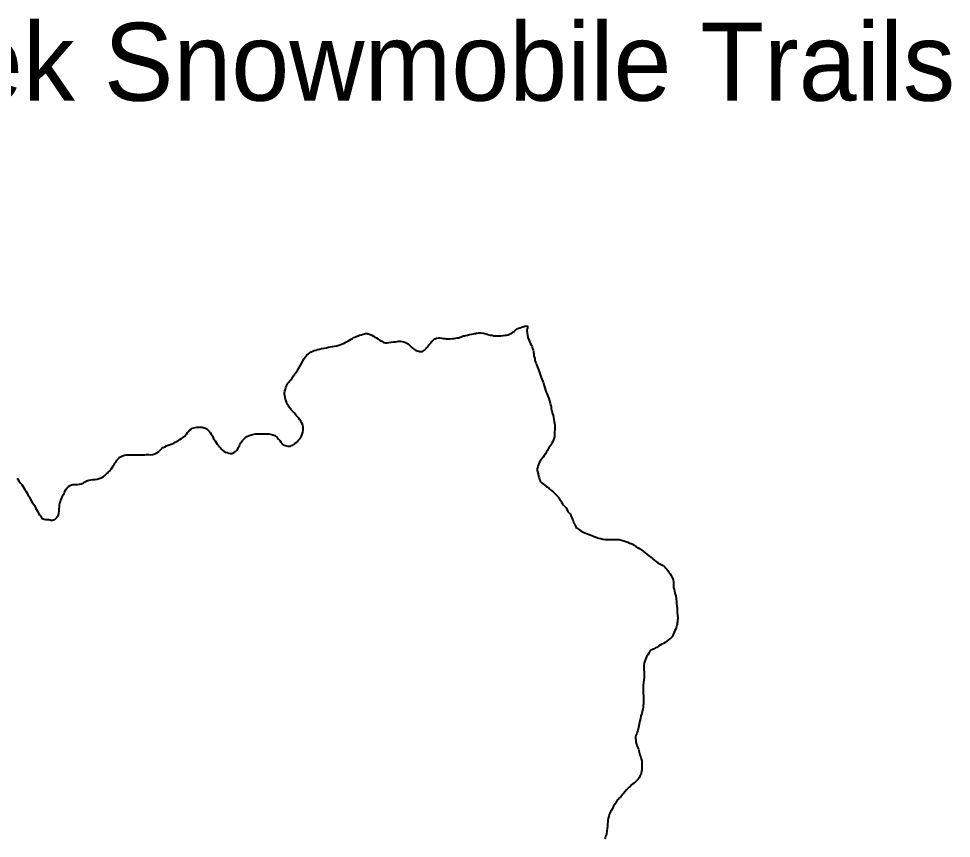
# Model space of a CAD drawing. Extents: x 322505 to 642419, y 5806860 to 5919753.
# Drawn here: x 555988 to 559579, y 5867430 to 5870588 of the extents above; entities that cross this region are included whole.
import ezdxf

# ---------------------------------------------------------------- set-up
doc = ezdxf.new("R2010")
doc.units = 0
doc.header["$LTSCALE"] = 140
doc.layers.add('5', color=7, linetype='Continuous', lineweight=40)

msp = doc.modelspace()

# ---------------------------------------------------------------- linework, layer by layer
at = {"layer": '5'}
for points in [[(557683, 5869358), (557697, 5869365), (557701, 5869366), (557705, 5869366), (557708, 5869367), (557716, 5869369), (557724, 5869371), (557732, 5869372), (557739, 5869374), (557744, 5869375), (557747, 5869375), (557750, 5869376), (557754, 5869376), (557758, 5869377), (557763, 5869377), (557769, 5869377), (557776, 5869376), (557782, 5869375), (557787, 5869374), (557792, 5869372), (557798, 5869370), (557804, 5869369), (557811, 5869368), (557818, 5869366), (557824, 5869366), (557831, 5869366), (557838, 5869366), (557845, 5869366), (557853, 5869367), (557861, 5869368), (557867, 5869369), (557873, 5869370), (557878, 5869372), (557883, 5869375), (557888, 5869378), (557892, 5869381), (557897, 5869384), (557901, 5869388), (557906, 5869391), (557909, 5869394), (557914, 5869396), (557921, 5869398), (557929, 5869401), (557937, 5869403), (557947, 5869405)], [(557947, 5869405), (557947, 5869403), (557947, 5869400), (557947, 5869397), (557946, 5869393), (557945, 5869386), (557946, 5869377), (557947, 5869368), (557949, 5869359), (557952, 5869351), (557955, 5869344), (557958, 5869338), (557962, 5869331), (557965, 5869323), (557967, 5869317), (557969, 5869311), (557970, 5869305), (557971, 5869300), (557972, 5869296), (557972, 5869291), (557973, 5869285), (557975, 5869278), (557976, 5869271), (557978, 5869265), (557980, 5869259), (557982, 5869254), (557984, 5869249), (557986, 5869245), (557988, 5869239), (557992, 5869228), (557996, 5869217), (558000, 5869206), (558004, 5869196), (558007, 5869188), (558009, 5869182), (558011, 5869174), (558014, 5869166), (558017, 5869157), (558019, 5869149), (558023, 5869141), (558026, 5869133), (558029, 5869125), (558032, 5869116), (558035, 5869107), (558036, 5869100), (558038, 5869093), (558039, 5869086), (558040, 5869081), (558041, 5869077), (558042, 5869072), (558044, 5869066), (558046, 5869059), (558048, 5869051), (558049, 5869044), (558050, 5869036), (558051, 5869029), (558052, 5869021), (558052, 5869013), (558052, 5869005), (558051, 5868998), (558051, 5868992), (558051, 5868987), (558051, 5868981), (558051, 5868977), (558050, 5868973), (558048, 5868966), (558045, 5868959), (558041, 5868952), (558037, 5868945), (558033, 5868940), (558030, 5868934), (558027, 5868930), (558024, 5868924), (558020, 5868919), (558016, 5868912), (558012, 5868905), (558007, 5868898), (558003, 5868892), (557999, 5868887), (557996, 5868883), (557994, 5868879), (557991, 5868873), (557988, 5868868), (557987, 5868862), (557986, 5868858), (557985, 5868855), (557985, 5868851), (557985, 5868847), (557986, 5868843), (557988, 5868834), (557990, 5868826), (557992, 5868819), (557994, 5868812), (557996, 5868807), (557999, 5868804), (558004, 5868799), (558009, 5868795), (558015, 5868790), (558021, 5868786), (558025, 5868783)], [(557255, 5869345), (557262, 5869349), (557268, 5869353), (557274, 5869356), (557278, 5869359), (557283, 5869361), (557288, 5869364), (557295, 5869366), (557301, 5869368), (557308, 5869370), (557314, 5869372), (557320, 5869374), (557323, 5869375), (557326, 5869375), (557330, 5869375), (557334, 5869374), (557339, 5869372), (557348, 5869369), (557355, 5869365), (557360, 5869361), (557366, 5869358), (557372, 5869354), (557376, 5869350), (557382, 5869347), (557387, 5869345), (557391, 5869342), (557395, 5869340), (557400, 5869339), (557407, 5869339), (557414, 5869340), (557422, 5869341), (557431, 5869343), (557439, 5869343), (557446, 5869344), (557452, 5869345), (557458, 5869345), (557465, 5869344), (557471, 5869343), (557477, 5869340), (557483, 5869338), (557488, 5869335), (557491, 5869332), (557496, 5869327), (557502, 5869321), (557508, 5869316), (557516, 5869311), (557524, 5869308), (557529, 5869307), (557532, 5869306), (557536, 5869305), (557540, 5869306), (557543, 5869306), (557547, 5869308), (557551, 5869311), (557554, 5869314), (557557, 5869317), (557559, 5869320), (557562, 5869323), (557565, 5869327), (557569, 5869332), (557572, 5869337), (557577, 5869341), (557581, 5869345), (557583, 5869348), (557586, 5869351), (557589, 5869354), (557592, 5869355), (557597, 5869357), (557604, 5869358), (557610, 5869358), (557617, 5869357), (557624, 5869356), (557629, 5869356), (557634, 5869355), (557638, 5869355), (557644, 5869355), (557650, 5869355), (557658, 5869356), (557665, 5869356), (557671, 5869357), (557677, 5869358), (557683, 5869358)], [(556931, 5868989), (556952, 5868988), (556963, 5868986), (556974, 5868982), (556984, 5868974), (556989, 5868968), (556994, 5868963), (556998, 5868957), (557001, 5868952), (557005, 5868948), (557009, 5868945), (557014, 5868943), (557019, 5868942), (557025, 5868941), (557030, 5868941), (557035, 5868941), (557039, 5868943), (557044, 5868945), (557048, 5868948), (557053, 5868952), (557059, 5868957), (557064, 5868963), (557069, 5868968), (557073, 5868972), (557076, 5868977), (557077, 5868980), (557079, 5868983), (557080, 5868987), (557081, 5868991), (557082, 5868995), (557083, 5869002), (557084, 5869009), (557084, 5869016), (557082, 5869023), (557079, 5869030), (557075, 5869037), (557071, 5869043), (557067, 5869049), (557062, 5869054), (557058, 5869058), (557054, 5869063), (557049, 5869069), (557044, 5869074), (557039, 5869080), (557034, 5869086), (557030, 5869091), (557027, 5869096), (557023, 5869101), (557021, 5869107), (557018, 5869115), (557016, 5869122), (557014, 5869129), (557013, 5869135), (557012, 5869141), (557012, 5869147), (557013, 5869153), (557015, 5869160), (557017, 5869167), (557019, 5869173), (557022, 5869179), (557025, 5869183), (557028, 5869188), (557032, 5869192), (557036, 5869197), (557041, 5869203), (557047, 5869212), (557052, 5869219), (557057, 5869226), (557062, 5869233), (557067, 5869241), (557072, 5869251), (557077, 5869260), (557082, 5869269), (557086, 5869277), (557092, 5869285), (557096, 5869289), (557099, 5869294), (557104, 5869297), (557109, 5869301), (557115, 5869304), (557121, 5869307), (557126, 5869310), (557132, 5869311), (557139, 5869313), (557146, 5869315), (557156, 5869317), (557165, 5869319), (557173, 5869320), (557180, 5869322), (557188, 5869323), (557196, 5869325), (557204, 5869326), (557213, 5869328), (557221, 5869330), (557229, 5869332), (557235, 5869335), (557241, 5869338), (557248, 5869341), (557255, 5869345)], [(556635, 5868987), (556638, 5868993), (556642, 5868997), (556646, 5869002), (556652, 5869006), (556658, 5869010), (556663, 5869012), (556668, 5869013), (556674, 5869014), (556681, 5869014), (556684, 5869014)], [(556684, 5869014), (556686, 5869014), (556690, 5869014), (556695, 5869014), (556699, 5869013), (556703, 5869012), (556708, 5869010), (556713, 5869008), (556717, 5869004), (556722, 5868999), (556726, 5868993), (556730, 5868987), (556734, 5868981), (556736, 5868977), (556738, 5868971), (556741, 5868967), (556745, 5868961), (556749, 5868955), (556753, 5868949), (556757, 5868944), (556762, 5868939), (556765, 5868934), (556769, 5868929), (556773, 5868925), (556779, 5868921), (556785, 5868918), (556791, 5868916), (556797, 5868914), (556802, 5868913), (556808, 5868913), (556809, 5868913)], [(556809, 5868913), (556813, 5868914), (556818, 5868916), (556823, 5868921), (556828, 5868926), (556832, 5868931), (556835, 5868937), (556838, 5868942), (556840, 5868948), (556842, 5868953), (556846, 5868958), (556850, 5868963), (556856, 5868969), (556861, 5868974), (556867, 5868978), (556873, 5868981), (556879, 5868983), (556889, 5868986), (556900, 5868988), (556910, 5868988), (556920, 5868989), (556931, 5868989)], [(556122, 5868657), (556127, 5868658), (556130, 5868661), (556133, 5868664), (556136, 5868668), (556138, 5868670), (556140, 5868673), (556142, 5868677), (556143, 5868683), (556144, 5868691), (556144, 5868699), (556145, 5868707), (556145, 5868714), (556147, 5868721), (556149, 5868727), (556151, 5868734), (556154, 5868741), (556157, 5868748), (556160, 5868754), (556163, 5868759), (556165, 5868764), (556167, 5868769), (556171, 5868775), (556175, 5868781), (556180, 5868786), (556186, 5868790), (556192, 5868792), (556197, 5868793), (556202, 5868793), (556208, 5868793), (556215, 5868793), (556222, 5868794), (556229, 5868796), (556236, 5868799), (556241, 5868802), (556246, 5868805), (556251, 5868807), (556258, 5868810), (556266, 5868811), (556274, 5868812), (556283, 5868812), (556291, 5868814), (556298, 5868816), (556306, 5868819), (556313, 5868823), (556320, 5868828), (556327, 5868834), (556331, 5868838), (556334, 5868842), (556338, 5868845), (556341, 5868849), (556344, 5868853), (556348, 5868859), (556352, 5868865), (556356, 5868870), (556359, 5868876), (556363, 5868881), (556366, 5868887), (556370, 5868891), (556375, 5868896), (556380, 5868900), (556386, 5868903), (556392, 5868905), (556397, 5868906), (556403, 5868907), (556409, 5868907), (556416, 5868907), (556424, 5868907), (556431, 5868907), (556437, 5868907), (556442, 5868908), (556448, 5868908), (556454, 5868908), (556461, 5868908), (556467, 5868908), (556474, 5868908), (556481, 5868909), (556489, 5868909), (556497, 5868908), (556505, 5868909), (556512, 5868911), (556520, 5868915), (556526, 5868919), (556532, 5868924), (556536, 5868928), (556540, 5868932), (556545, 5868936), (556551, 5868939), (556557, 5868942), (556564, 5868945), (556572, 5868947), (556579, 5868950), (556586, 5868953), (556591, 5868956), (556597, 5868959), (556603, 5868963), (556608, 5868966)], [(556608, 5868966), (556609, 5868967), (556615, 5868971), (556619, 5868974), (556624, 5868977), (556628, 5868979), (556631, 5868983), (556635, 5868987)], [(555983, 5868818), (555989, 5868808), (555995, 5868799), (556000, 5868793), (556004, 5868787), (556008, 5868781), (556012, 5868774), (556017, 5868766), (556021, 5868760), (556024, 5868754), (556027, 5868748), (556030, 5868743), (556038, 5868729), (556041, 5868723), (556043, 5868721), (556049, 5868712), (556054, 5868701), (556061, 5868691), (556065, 5868683), (556069, 5868677), (556073, 5868671), (556076, 5868666), (556079, 5868663), (556082, 5868661), (556086, 5868660), (556092, 5868659), (556098, 5868658), (556105, 5868658), (556110, 5868657), (556114, 5868656), (556118, 5868656), (556122, 5868657)], [(558025, 5868783), (558028, 5868781), (558029, 5868780), (558032, 5868777), (558036, 5868773), (558040, 5868770), (558046, 5868765), (558051, 5868760), (558057, 5868755), (558062, 5868750), (558065, 5868746), (558068, 5868742), (558071, 5868737), (558075, 5868731), (558078, 5868725), (558082, 5868719), (558085, 5868715), (558088, 5868711)], [(558088, 5868711), (558092, 5868707), (558096, 5868703), (558099, 5868697), (558103, 5868691), (558107, 5868685), (558111, 5868680), (558114, 5868674), (558116, 5868670), (558117, 5868667), (558119, 5868663), (558121, 5868659), (558123, 5868654), (558124, 5868650), (558126, 5868645), (558129, 5868640), (558131, 5868635), (558133, 5868630), (558133, 5868628)], [(558133, 5868628), (558136, 5868626), (558143, 5868621), (558152, 5868615), (558162, 5868610), (558175, 5868605), (558188, 5868599), (558201, 5868594), (558211, 5868590), (558221, 5868587), (558230, 5868585), (558237, 5868583), (558246, 5868582), (558256, 5868582), (558266, 5868582), (558275, 5868582), (558284, 5868582), (558292, 5868581), (558300, 5868581), (558309, 5868579), (558318, 5868576), (558326, 5868574), (558334, 5868571), (558340, 5868568), (558346, 5868566), (558352, 5868563), (558358, 5868560), (558365, 5868555), (558373, 5868550), (558380, 5868545), (558387, 5868540), (558394, 5868535), (558400, 5868530), (558407, 5868525), (558414, 5868519), (558422, 5868513), (558428, 5868508), (558434, 5868503), (558439, 5868499), (558444, 5868496), (558449, 5868492), (558454, 5868489), (558459, 5868487), (558465, 5868484), (558470, 5868482), (558471, 5868482)], [(558471, 5868482), (558475, 5868478), (558479, 5868473), (558483, 5868468), (558487, 5868462), (558492, 5868455), (558496, 5868449), (558500, 5868443), (558503, 5868438), (558506, 5868434), (558507, 5868430), (558508, 5868426), (558509, 5868419), (558510, 5868412), (558510, 5868404), (558510, 5868396), (558512, 5868390), (558513, 5868383), (558515, 5868377), (558516, 5868371), (558518, 5868364), (558520, 5868353), (558521, 5868343), (558521, 5868334), (558522, 5868325), (558523, 5868318), (558524, 5868311), (558524, 5868301), (558524, 5868300)], [(558524, 5868300), (558525, 5868290), (558526, 5868279), (558525, 5868269), (558525, 5868264), (558524, 5868260), (558524, 5868256), (558522, 5868251), (558521, 5868247), (558518, 5868238), (558515, 5868231), (558512, 5868224), (558510, 5868218)], [(558510, 5868218), (558507, 5868212), (558504, 5868207), (558499, 5868201), (558492, 5868196), (558484, 5868190), (558477, 5868185), (558471, 5868181), (558464, 5868178), (558458, 5868174), (558452, 5868171), (558445, 5868166), (558440, 5868164), (558436, 5868161), (558432, 5868159), (558428, 5868158), (558426, 5868157), (558422, 5868155), (558418, 5868151), (558414, 5868144), (558410, 5868137), (558406, 5868130), (558403, 5868123), (558400, 5868117), (558398, 5868110), (558397, 5868104), (558395, 5868096), (558395, 5868088), (558395, 5868079), (558396, 5868070), (558396, 5868063), (558397, 5868057), (558396, 5868050), (558395, 5868041), (558394, 5868031), (558393, 5868020), (558392, 5868010), (558392, 5867999), (558393, 5867989), (558394, 5867979), (558394, 5867968), (558394, 5867957), (558394, 5867949), (558393, 5867942), (558392, 5867935), (558391, 5867929), (558390, 5867924), (558389, 5867918), (558387, 5867911), (558384, 5867902), (558382, 5867892), (558380, 5867883), (558378, 5867877), (558377, 5867870), (558376, 5867864), (558375, 5867858), (558373, 5867852), (558372, 5867846), (558370, 5867840), (558368, 5867834), (558366, 5867829), (558364, 5867826), (558363, 5867822), (558363, 5867816), (558364, 5867810), (558365, 5867803), (558366, 5867797), (558368, 5867791), (558370, 5867785), (558372, 5867779), (558374, 5867774), (558376, 5867768), (558377, 5867762), (558379, 5867757), (558380, 5867751), (558382, 5867746), (558383, 5867743), (558385, 5867737), (558387, 5867729), (558388, 5867721), (558388, 5867711), (558388, 5867702), (558387, 5867695), (558386, 5867688), (558385, 5867681), (558383, 5867675), (558380, 5867670), (558377, 5867664), (558373, 5867659), (558369, 5867654), (558365, 5867650), (558361, 5867646), (558358, 5867643), (558353, 5867640), (558348, 5867636), (558344, 5867632), (558339, 5867628), (558333, 5867623), (558328, 5867617)], [(558328, 5867617), (558323, 5867611), (558318, 5867605), (558314, 5867601), (558310, 5867596), (558306, 5867591), (558302, 5867586), (558297, 5867581), (558293, 5867577), (558290, 5867573), (558289, 5867570)], [(558289, 5867570), (558288, 5867569), (558285, 5867564), (558282, 5867559), (558279, 5867554), (558276, 5867548), (558273, 5867543), (558270, 5867537), (558267, 5867532), (558264, 5867528), (558262, 5867523), (558260, 5867515), (558258, 5867508), (558256, 5867501), (558256, 5867494), (558255, 5867486), (558255, 5867477), (558254, 5867468), (558253, 5867458), (558251, 5867448), (558250, 5867442), (558248, 5867437), (558246, 5867433), (558245, 5867429)]]:
    msp.add_lwpolyline(points, dxfattribs=at)

# ---------------------------------------------------------------- texts
msp.add_text('Deacon Creek Snowmobile Trails', height=300, dxfattribs=at).set_placement((553640.5, 5870271.6))

doc.saveas('drawing.dxf')
